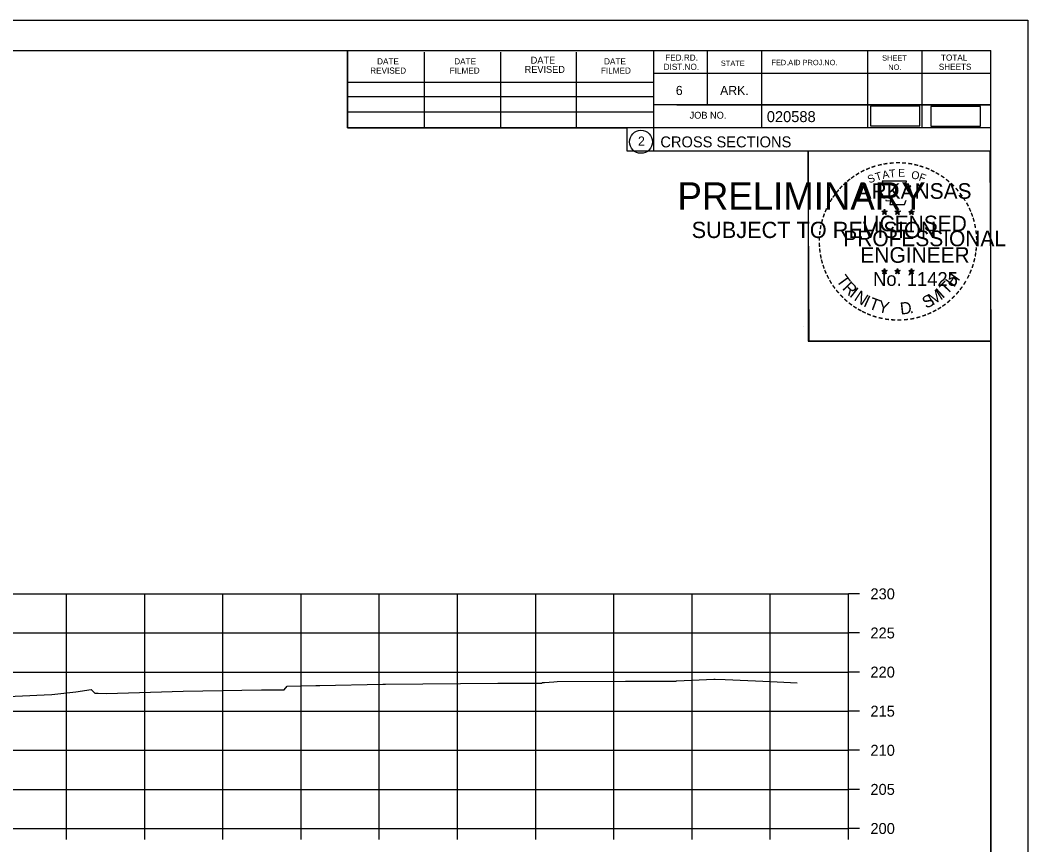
# Model space of a CAD drawing. Extents: x 1368968 to 1369915, y 377395 to 380381.
# Drawn here: x 1369785.9 to 1369914.7, y 378142.6 to 378248 of the extents above; entities that cross this region are included whole.
import ezdxf

# ---------------------------------------------------------------- set-up
doc = ezdxf.new("R2010")
doc.units = 0
for name, color, linetype in [('Default', 7, 'Continuous'), ('S_BREAKLINE_ANNOT', 7, 'Continuous'), ('S_BRIDGE', 7, 'Continuous'), ('S_BRIDGE_ANNOT', 7, 'Continuous'), ('S_BUILDING_ANNOT', 7, 'Continuous'), ('S_CAL_CORNER', 7, 'Continuous'), ('S_CTL_TABLE', 7, 'Continuous'), ('S_DITCHLINE_ANNOT', 7, 'Continuous'), ('S_DROP_INLET', 7, 'Continuous')]:
    doc.layers.add(name, color=color, linetype=linetype)

msp = doc.modelspace()

# ---------------------------------------------------------------- linework, layer by layer
at = {"layer": 'Default'}
for points in [[(1369894.57, 378234.53), (1369900.91, 378234.53), (1369900.91, 378237.05), (1369894.57, 378237.05)], [(1369902.31, 378234.48), (1369908.65, 378234.48), (1369908.65, 378237), (1369902.31, 378237)]]:
    msp.add_lwpolyline(points, close=True, dxfattribs=at)
at = {"layer": 'S_BREAKLINE_ANNOT'}
for p, q in [((1369891.78, 378144.69), (1369891.78, 378174.69)), ((1369893.18, 378174.69), (1369891.78, 378174.69)), ((1369893.18, 378169.69), (1369891.78, 378169.69)), ((1369893.18, 378164.69), (1369891.78, 378164.69)), ((1369893.18, 378159.69), (1369891.78, 378159.69)), ((1369893.18, 378154.69), (1369891.78, 378154.69)), ((1369893.18, 378149.69), (1369891.78, 378149.69)), ((1369611.78, 378144.69), (1369891.78, 378144.69)), ((1369791.78, 378143.29), (1369791.78, 378144.69)), ((1369801.78, 378143.29), (1369801.78, 378144.69)), ((1369811.78, 378143.29), (1369811.78, 378144.69)), ((1369821.78, 378143.29), (1369821.78, 378144.69)), ((1369831.78, 378143.29), (1369831.78, 378144.69)), ((1369841.78, 378143.29), (1369841.78, 378144.69)), ((1369851.78, 378143.29), (1369851.78, 378144.69)), ((1369861.78, 378143.29), (1369861.78, 378144.69)), ((1369871.78, 378143.29), (1369871.78, 378144.69)), ((1369881.78, 378143.29), (1369881.78, 378144.69)), ((1369891.78, 378143.29), (1369891.78, 378144.69)), ((1369893.18, 378144.69), (1369891.78, 378144.69))]:
    msp.add_line(p, q, dxfattribs=at)
at = {"layer": 'S_BRIDGE_ANNOT'}
for p, q in [((1369593.78, 378244.15), (1369909.96, 378244.15)), ((1369827.7, 378234.27), (1369827.7, 378244.15)), ((1369866.86, 378244.15), (1369866.86, 378231.35)), ((1369873.7, 378244.15), (1369873.7, 378237.21)), ((1369880.64, 378244.15), (1369880.64, 378234.27)), ((1369894.22, 378244.15), (1369894.22, 378234.27)), ((1369901.16, 378244.15), (1369901.16, 378234.27)), ((1369909.96, 378038.69), (1369909.96, 378244.15)), ((1369837.56, 378234.27), (1369837.56, 378243.95)), ((1369847.32, 378234.27), (1369847.32, 378243.95)), ((1369857, 378234.27), (1369857, 378243.95)), ((1369909.96, 378241.21), (1369866.86, 378241.21)), ((1369909.96, 378241.23), (1369909.96, 378241.23)), ((1369827.7, 378240.13), (1369866.86, 378240.13)), ((1369827.7, 378238.27), (1369866.86, 378238.27)), ((1369827.7, 378234.27), (1369827.7, 378236.33)), ((1369827.7, 378236.33), (1369866.86, 378236.33)), ((1369909.96, 378237.21), (1369866.86, 378237.21)), ((1369869.82, 378237.21), (1369909.96, 378237.21)), ((1369909.96, 378234.27), (1369827.7, 378234.27)), ((1369866.86, 378231.35), (1369909.96, 378231.35))]:
    msp.add_line(p, q, dxfattribs=at)
msp.add_circle((1369865.24, 378232.49), 1.47, dxfattribs=at)
at = {"layer": 'S_BUILDING_ANNOT'}
for p, q in [((1369896.04, 378223.61), (1369896.39, 378223.5)), ((1369896.04, 378223.61), (1369896.29, 378223.56)), ((1369896.04, 378223.61), (1369896.28, 378223.48)), ((1369896.17, 378223.2), (1369896.39, 378223.5)), ((1369896.17, 378223.2), (1369896.3, 378223.44)), ((1369896.39, 378223.86), (1369896.35, 378223.61)), ((1369896.39, 378223.5), (1369896.39, 378223.86)), ((1369896.39, 378223.86), (1369896.44, 378223.61)), ((1369896.74, 378223.61), (1369896.39, 378223.5)), ((1369896.6, 378223.2), (1369896.39, 378223.5)), ((1369896.74, 378223.61), (1369896.45, 378223.56)), ((1369896.6, 378223.2), (1369896.47, 378223.49)), ((1369896.74, 378223.61), (1369896.53, 378223.5)), ((1369897.71, 378223.61), (1369898.06, 378223.5)), ((1369897.71, 378223.61), (1369897.96, 378223.56)), ((1369897.71, 378223.61), (1369897.95, 378223.48)), ((1369897.84, 378223.2), (1369898.06, 378223.5)), ((1369897.84, 378223.2), (1369897.97, 378223.44)), ((1369898.06, 378223.86), (1369898.02, 378223.61)), ((1369898.06, 378223.5), (1369898.06, 378223.86)), ((1369898.06, 378223.86), (1369898.11, 378223.61)), ((1369898.41, 378223.61), (1369898.06, 378223.5)), ((1369898.27, 378223.2), (1369898.06, 378223.5)), ((1369898.41, 378223.61), (1369898.12, 378223.56)), ((1369898.27, 378223.2), (1369898.14, 378223.49)), ((1369898.41, 378223.61), (1369898.2, 378223.5)), ((1369899.48, 378223.59), (1369899.82, 378223.48)), ((1369899.48, 378223.59), (1369899.73, 378223.55)), ((1369899.48, 378223.59), (1369899.71, 378223.47)), ((1369899.61, 378223.19), (1369899.82, 378223.48)), ((1369899.61, 378223.19), (1369899.73, 378223.43)), ((1369899.82, 378223.85), (1369899.78, 378223.6)), ((1369899.82, 378223.48), (1369899.82, 378223.85)), ((1369899.82, 378223.85), (1369899.87, 378223.6)), ((1369900.17, 378223.59), (1369899.82, 378223.48)), ((1369900.04, 378223.19), (1369899.82, 378223.48)), ((1369900.17, 378223.59), (1369899.89, 378223.55)), ((1369900.04, 378223.19), (1369899.9, 378223.48)), ((1369900.17, 378223.59), (1369899.97, 378223.49)), ((1369896.17, 378223.2), (1369896.39, 378223.42)), ((1369896.6, 378223.2), (1369896.39, 378223.41)), ((1369897.84, 378223.2), (1369898.06, 378223.42)), ((1369898.27, 378223.2), (1369898.06, 378223.41)), ((1369899.61, 378223.19), (1369899.82, 378223.4)), ((1369900.04, 378223.19), (1369899.82, 378223.4)), ((1369896.04, 378216.03), (1369896.39, 378215.92)), ((1369896.04, 378216.03), (1369896.29, 378215.99)), ((1369896.04, 378216.03), (1369896.27, 378215.91)), ((1369896.17, 378215.63), (1369896.39, 378215.92)), ((1369896.17, 378215.63), (1369896.3, 378215.87)), ((1369896.17, 378215.63), (1369896.38, 378215.84)), ((1369896.39, 378216.29), (1369896.35, 378216.04)), ((1369896.6, 378215.63), (1369896.38, 378215.84)), ((1369896.39, 378215.92), (1369896.39, 378216.29)), ((1369896.39, 378216.29), (1369896.44, 378216.04)), ((1369896.73, 378216.03), (1369896.39, 378215.92)), ((1369896.6, 378215.63), (1369896.39, 378215.92)), ((1369896.73, 378216.03), (1369896.45, 378215.98)), ((1369896.6, 378215.63), (1369896.46, 378215.92)), ((1369896.73, 378216.03), (1369896.53, 378215.93)), ((1369897.71, 378216.03), (1369898.06, 378215.92)), ((1369897.71, 378216.03), (1369897.96, 378215.99)), ((1369897.71, 378216.03), (1369897.94, 378215.91)), ((1369897.84, 378215.63), (1369898.06, 378215.92)), ((1369897.84, 378215.63), (1369897.97, 378215.87)), ((1369897.84, 378215.63), (1369898.05, 378215.84)), ((1369898.06, 378216.29), (1369898.01, 378216.04)), ((1369898.27, 378215.63), (1369898.05, 378215.84)), ((1369898.06, 378215.92), (1369898.06, 378216.29)), ((1369898.06, 378216.29), (1369898.1, 378216.04)), ((1369898.4, 378216.03), (1369898.06, 378215.92)), ((1369898.27, 378215.63), (1369898.06, 378215.92)), ((1369898.4, 378216.03), (1369898.12, 378215.98)), ((1369898.27, 378215.63), (1369898.13, 378215.92)), ((1369898.4, 378216.03), (1369898.2, 378215.93)), ((1369899.47, 378216.02), (1369899.82, 378215.91)), ((1369899.47, 378216.02), (1369899.73, 378215.98)), ((1369899.47, 378216.02), (1369899.71, 378215.9)), ((1369899.61, 378215.62), (1369899.82, 378215.91)), ((1369899.61, 378215.62), (1369899.73, 378215.86)), ((1369899.61, 378215.62), (1369899.82, 378215.83)), ((1369899.82, 378216.28), (1369899.78, 378216.03)), ((1369899.82, 378215.91), (1369899.82, 378216.28)), ((1369899.82, 378216.28), (1369899.87, 378216.03)), ((1369900.17, 378216.02), (1369899.82, 378215.91)), ((1369900.04, 378215.62), (1369899.82, 378215.91)), ((1369900.04, 378215.62), (1369899.82, 378215.83)), ((1369900.17, 378216.02), (1369899.88, 378215.97)), ((1369900.04, 378215.62), (1369899.9, 378215.91)), ((1369900.17, 378216.02), (1369899.97, 378215.92))]:
    msp.add_line(p, q, dxfattribs=at)
for points in [[(1369896.08, 378227.48), (1369896.35, 378226.66)], [(1369899.59, 378226.56), (1369899.74, 378226.85), (1369899.05, 378226.82), (1369899.2, 378227.48), (1369896.08, 378227.48)], [(1369896.57, 378225.06), (1369896.57, 378224.97), (1369897.14, 378224.96), (1369897.08, 378224.48), (1369898.95, 378224.48), (1369899.15, 378225.02)], [(1369896.39, 378223.86), (1369896.6, 378223.2), (1369896.04, 378223.61), (1369896.74, 378223.61), (1369896.17, 378223.2), (1369896.39, 378223.86)], [(1369898.06, 378223.86), (1369898.27, 378223.2), (1369897.71, 378223.61), (1369898.41, 378223.61), (1369897.84, 378223.2), (1369898.06, 378223.86)], [(1369899.82, 378223.85), (1369900.04, 378223.19), (1369899.48, 378223.59), (1369900.17, 378223.59), (1369899.61, 378223.19), (1369899.82, 378223.85)], [(1369896.39, 378216.29), (1369896.6, 378215.63), (1369896.04, 378216.03), (1369896.73, 378216.03), (1369896.17, 378215.63), (1369896.39, 378216.29)], [(1369898.06, 378216.29), (1369898.27, 378215.63), (1369897.71, 378216.03), (1369898.4, 378216.03), (1369897.84, 378215.63), (1369898.06, 378216.29)], [(1369899.82, 378216.28), (1369900.04, 378215.62), (1369899.47, 378216.02), (1369900.17, 378216.02), (1369899.61, 378215.62), (1369899.82, 378216.28)]]:
    msp.add_lwpolyline(points, dxfattribs=at)
for centre, radius in [((1369896.39, 378223.49), 0.172), ((1369896.39, 378223.49), 0.145), ((1369896.39, 378223.49), 0.116), ((1369896.39, 378223.49), 0.0991), ((1369896.39, 378223.49), 0.0747), ((1369896.39, 378223.49), 0.0495), ((1369896.39, 378223.49), 0.0296), ((1369898.06, 378223.49), 0.172), ((1369898.06, 378223.49), 0.145), ((1369898.06, 378223.49), 0.116), ((1369898.06, 378223.49), 0.0991), ((1369898.06, 378223.49), 0.0747), ((1369898.06, 378223.49), 0.0495), ((1369898.06, 378223.49), 0.0296), ((1369899.82, 378223.48), 0.172), ((1369899.82, 378223.48), 0.145), ((1369899.82, 378223.48), 0.116), ((1369899.82, 378223.48), 0.0991), ((1369899.82, 378223.48), 0.0747), ((1369899.82, 378223.48), 0.0495), ((1369899.82, 378223.48), 0.0296), ((1369896.39, 378215.92), 0.172), ((1369896.39, 378215.92), 0.145), ((1369896.39, 378215.92), 0.116), ((1369896.39, 378215.92), 0.0991), ((1369896.39, 378215.92), 0.0747), ((1369896.39, 378215.92), 0.0495), ((1369896.39, 378215.92), 0.0296), ((1369898.05, 378215.92), 0.172), ((1369898.05, 378215.92), 0.145), ((1369898.05, 378215.92), 0.116), ((1369898.05, 378215.92), 0.0991), ((1369898.05, 378215.92), 0.0747), ((1369898.05, 378215.92), 0.0495), ((1369898.05, 378215.92), 0.0296), ((1369899.82, 378215.91), 0.172), ((1369899.82, 378215.91), 0.145), ((1369899.82, 378215.91), 0.116), ((1369899.82, 378215.91), 0.0991), ((1369899.82, 378215.91), 0.0747), ((1369899.82, 378215.91), 0.0495), ((1369899.82, 378215.91), 0.0296)]:
    msp.add_circle(centre, radius, dxfattribs=at)
at = {"layer": 'S_CTL_TABLE'}
msp.add_lwpolyline([(1369782.41, 378161.48), (1369788.93, 378161.8), (1369789.89, 378161.84), (1369792.99, 378162.18), (1369794.94, 378162.45), (1369795.3, 378162.12), (1369795.42, 378161.99), (1369795.84, 378161.99), (1369796.91, 378161.96), (1369802.52, 378162.13), (1369806.69, 378162.26), (1369816.72, 378162.41), (1369818, 378162.43), (1369819.41, 378162.4), (1369819.56, 378162.4), (1369819.6, 378162.44), (1369819.99, 378162.87), (1369823.66, 378162.98), (1369824.19, 378162.99), (1369832.25, 378163.13), (1369832.56, 378163.14), (1369846.92, 378163.28), (1369852.51, 378163.29), (1369852.63, 378163.36), (1369852.91, 378163.37), (1369854.09, 378163.46), (1369854.11, 378163.46), (1369854.51, 378163.47), (1369863.27, 378163.54), (1369869.69, 378163.51), (1369869.78, 378163.59), (1369869.78, 378163.59), (1369869.82, 378163.59), (1369874.54, 378163.8), (1369874.71, 378163.79), (1369876.02, 378163.73), (1369881.8, 378163.49), (1369885.21, 378163.3)], dxfattribs=at)
at = {"layer": 'S_DITCHLINE_ANNOT'}
for p, q in [((1369611.78, 378174.69), (1369891.78, 378174.69)), ((1369791.78, 378144.69), (1369791.78, 378174.69)), ((1369801.78, 378144.69), (1369801.78, 378174.69)), ((1369811.78, 378144.69), (1369811.78, 378174.69)), ((1369821.78, 378144.69), (1369821.78, 378174.69)), ((1369831.78, 378144.69), (1369831.78, 378174.69)), ((1369841.78, 378144.69), (1369841.78, 378174.69)), ((1369851.78, 378144.69), (1369851.78, 378174.69)), ((1369861.78, 378144.69), (1369861.78, 378174.69)), ((1369871.78, 378144.69), (1369871.78, 378174.69)), ((1369881.78, 378144.69), (1369881.78, 378174.69)), ((1369891.78, 378144.69), (1369891.78, 378174.69)), ((1369611.78, 378169.69), (1369891.78, 378169.69)), ((1369611.78, 378164.69), (1369891.78, 378164.69)), ((1369611.78, 378159.69), (1369891.78, 378159.69)), ((1369611.78, 378154.69), (1369891.78, 378154.69)), ((1369611.78, 378149.69), (1369891.78, 378149.69)), ((1369611.78, 378144.69), (1369891.78, 378144.69))]:
    msp.add_line(p, q, dxfattribs=at)
at = {"layer": 'S_DROP_INLET'}
for p, q in [((1369581.38, 378248.05), (1369914.71, 378248.05)), ((1369885.99, 378208.9), (1369885.99, 378208.9))]:
    msp.add_line(p, q, dxfattribs=at)
for points in [[(1369581.37, 378248.05), (1369914.71, 378248.05), (1369914.71, 378034.71), (1369581.37, 378034.71)], [(1369827.7, 378244.15), (1369827.7, 378234.27), (1369863.43, 378234.27), (1369863.43, 378231.35), (1369886.63, 378231.35), (1369886.63, 378207.02), (1369909.96, 378207.02), (1369909.96, 378038.69), (1369593.78, 378038.69), (1369593.78, 378244.15)], [(1369886.63, 378231.35), (1369909.84, 378231.35), (1369909.96, 378207.02), (1369886.75, 378207.02)]]:
    msp.add_lwpolyline(points, close=True, dxfattribs=at)

# ---------------------------------------------------------------- texts
at = {"layer": 'S_BRIDGE'}
for s, p in [('230', (1369894.58, 378173.99)), ('225', (1369894.58, 378168.99)), ('220', (1369894.58, 378163.99)), ('215', (1369894.58, 378158.99)), ('210', (1369894.58, 378153.99)), ('205', (1369894.58, 378148.99)), ('200', (1369894.58, 378143.99))]:
    msp.add_text(s, height=1.4, dxfattribs=at).set_placement(p)
at = {"layer": 'S_BRIDGE_ANNOT'}
for s, height, p in [('DATE', 0.782, (1369831.5, 378242.39)), ('DATE', 0.782, (1369841.36, 378242.39)), ('DATE', 0.879, (1369851.14, 378242.49)), ('DATE', 0.782, (1369860.52, 378242.39)), ('FED.RD.', 0.782, (1369868.34, 378242.87)), ('STATE', 0.684, (1369875.46, 378242.19)), ('FED.AID PROJ.NO.', 0.684, (1369881.92, 378242.29)), ('SHEET', 0.684, (1369896.08, 378242.87)), ('TOTAL', 0.782, (1369903.6, 378242.87)), ('REVISED', 0.782, (1369830.62, 378241.21)), ('FILMED', 0.782, (1369840.78, 378241.21)), ('REVISED', 0.879, (1369850.36, 378241.31)), ('FILMED', 0.782, (1369860.12, 378241.21)), ('DIST.NO.', 0.782, (1369868.14, 378241.69)), ('NO.', 0.684, (1369896.86, 378241.69)), ('SHEETS', 0.782, (1369903.32, 378241.69)), ('6', 1.17, (1369869.7, 378238.47)), ('ARK.', 1.172, (1369875.36, 378238.47)), ('JOB NO.', 0.879, (1369871.46, 378235.45)), ('020588', 1.4, (1369881.33, 378235.01)), ('2', 1.17, (1369864.86, 378232)), ('CROSS SECTIONS', 1.4, (1369867.72, 378231.78))]:
    msp.add_text(s, height=height, rotation=360, dxfattribs=at).set_placement(p)
at = {"layer": 'S_BUILDING_ANNOT'}
for s, height, rotation, p in [('-', 1.6, 5.8968, (1369896.99, 378229.12)), ('-', 1.6, 0.1862, (1369897.76, 378229.2)), ('-', 1.6, 357.743, (1369898.48, 378229.18)), ('-', 1.6, 34.0636, (1369892.97, 378227.66)), ('-', 1.6, 28.7918, (1369893.56, 378228.03)), ('-', 1.6, 24.3072, (1369894.2, 378228.34)), ('-', 1.6, 19.1761, (1369894.83, 378228.61)), ('T', 1, 16.4036, (1369895.35, 378227.49)), ('-', 1.6, 13.6301, (1369895.58, 378228.85)), ('A', 1, 11.2132, (1369896.18, 378227.74)), ('-', 1.6, 10.2193, (1369896.26, 378229.01)), ('T', 1, 6.0228, (1369897.03, 378227.91)), ('E', 1, 0.8323, (1369898.13, 378228.02)), ('-', 1.6, 352.1617, (1369899.23, 378229.13)), ('O', 1, 350.4515, (1369899.74, 378227.81)), ('-', 1.6, 347.2049, (1369899.95, 378229.01)), ('-', 1.6, 342.3362, (1369900.58, 378228.86)), ('-', 1.6, 337.8551, (1369901.32, 378228.64)), ('-', 1.6, 334.1211, (1369901.95, 378228.36)), ('-', 1.6, 329.6409, (1369902.53, 378228.08)), ('-', 1.6, 42.9622, (1369891.48, 378226.47)), ('-', 1.6, 38.9507, (1369891.91, 378226.88)), ('-', 1.6, 36.2317, (1369892.39, 378227.26)), ('S', 1, 21.594, (1369894.44, 378227.16)), ('F', 1, 340.0707, (1369900.69, 378227.58)), ('-', 1.6, 325.8627, (1369903.17, 378227.72)), ('-', 1.6, 320.5297, (1369903.78, 378227.29)), ('-', 1.6, 50.6142, (1369890.63, 378225.5)), ('-', 1.6, 48.423, (1369891.03, 378225.99)), ('ARKANSAS', 2, 360, (1369892.94, 378225.2)), ('-', 1.6, 315.5786, (1369904.38, 378226.81)), ('-', 1.6, 309.8797, (1369904.95, 378226.26)), ('-', 1.6, 58.0706, (1369889.89, 378224.41)), ('-', 1.6, 54.2325, (1369890.22, 378224.93)), ('-', 1.6, 306.6522, (1369905.47, 378225.65)), ('-', 1.4, 303.6753, (1369905.96, 378225.09)), ('-', 1.6, 299.6684, (1369906.28, 378224.48)), ('-', 1.6, 67.7743, (1369889.32, 378223.18)), ('-', 1.6, 62.8713, (1369889.58, 378223.79)), ('DWB', 0.01, 360, (1369896.38, 378223.49)), ('DWB', 0.01, 360, (1369898.05, 378223.49)), ('DWB', 0.01, 360, (1369899.81, 378223.48)), ('-', 1.6, 294.6628, (1369906.6, 378223.87)), ('-', 1.6, 290.5728, (1369906.86, 378223.29)), ('-', 1.6, 75.461, (1369888.9, 378221.84)), ('-', 1.6, 72.3945, (1369889.1, 378222.55)), ('LICENSED', 2, 360, (1369893.53, 378221.05)), ('-', 1.6, 285.1233, (1369907.09, 378222.71)), ('-', 1.6, 85.1863, (1369888.69, 378220.43)), ('-', 1.6, 81.2013, (1369888.77, 378221.13)), ('PROFESSIONAL', 2, 360, (1369891.11, 378219.14)), ('-', 1.6, 280.5493, (1369907.29, 378221.97)), ('-', 1.6, 276.5962, (1369907.45, 378221.2)), ('-', 1.6, 94.1959, (1369888.7, 378219.01)), ('-', 1.6, 89.0622, (1369888.67, 378219.73)), ('-', 1.6, 274.3301, (1369907.51, 378220.48)), ('-', 1.6, 269.9407, (1369907.55, 378219.85)), ('-', 1.6, 98.9479, (1369888.78, 378218.34)), ('ENGINEER', 2, 360, (1369893.3, 378217.02)), ('-', 1.6, 260.9953, (1369907.46, 378218.53)), ('-', 1.6, 263.5172, (1369907.53, 378219.18)), ('-', 1.6, 101.7149, (1369888.91, 378217.61)), ('-', 1.6, 105.4578, (1369889.07, 378217.01)), ('-', 1.6, 255.7626, (1369907.35, 378217.85)), ('-', 1.6, 109.0874, (1369889.29, 378216.38)), ('-', 1.6, 114.0643, (1369889.54, 378215.79)), ('No. 11425', 1.757, 360, (1369894.92, 378214.07)), ('DWB', 0.01, 360, (1369896.37, 378215.92)), ('DWB', 0.01, 360, (1369898.04, 378215.92)), ('DWB', 0.01, 360, (1369899.81, 378215.91)), ('H', 1.54, 54.6088, (1369905.27, 378213.8)), ('-', 1.6, 247.8887, (1369906.94, 378216.46)), ('-', 1.6, 252.8681, (1369907.17, 378217.13)), ('-', 1.6, 115.7289, (1369889.85, 378215.17)), ('-', 1.6, 120.4471, (1369890.2, 378214.58)), ('T', 1.54, 306.0406, (1369890.15, 378214.76)), ('R', 1.54, 314.005, (1369890.91, 378213.71)), ('T', 1.54, 46.6444, (1369904.38, 378212.85)), ('-', 1.6, 239.0712, (1369906.29, 378215.07)), ('-', 1.6, 244.6197, (1369906.68, 378215.83)), ('-', 1.6, 125.8934, (1369890.61, 378214.02)), ('-', 1.6, 130.7181, (1369891.07, 378213.47)), ('I', 1.54, 321.9694, (1369891.81, 378212.78)), ('N', 1.54, 326.5002, (1369892.38, 378212.31)), ('M', 1.54, 32.6563, (1369902.53, 378211.53)), ('I', 1.54, 42.1136, (1369903.81, 378212.37)), ('-', 1.6, 231.2538, (1369905.46, 378213.86)), ('-', 1.6, 233.8452, (1369905.89, 378214.42)), ('-', 1.6, 134.2238, (1369891.59, 378212.92)), ('-', 1.6, 138.9338, (1369892.11, 378212.46)), ('-', 1.6, 144.6463, (1369892.67, 378212.05)), ('I', 1.54, 335.3603, (1369893.58, 378211.52)), ('T', 1.54, 339.8912, (1369894.25, 378211.2)), ('Y', 1.54, 347.8556, (1369895.46, 378210.75)), ('D', 1.54, 6.3969, (1369898.45, 378210.39)), ('S', 1.54, 26.9312, (1369901.69, 378211.12)), ('-', 1.6, 221.0851, (1369904.45, 378212.78)), ('-', 1.6, 225.7653, (1369904.98, 378213.29)), ('-', 1.6, 148.0898, (1369893.23, 378211.68)), ('-', 1.6, 151.5704, (1369893.81, 378211.36)), ('-', 1.6, 154.6002, (1369894.33, 378211.11)), ('-', 1.6, 158.5612, (1369894.95, 378210.86)), ('.', 1.54, 13.7642, (1369899.64, 378210.52)), ('-', 1.6, 204.2516, (1369902.19, 378211.26)), ('-', 1.6, 207.3568, (1369902.81, 378211.58)), ('-', 1.6, 212.2491, (1369903.37, 378211.92)), ('-', 1.6, 215.7363, (1369903.91, 378212.31)), ('-', 1.6, 162.7983, (1369895.64, 378210.64)), ('-', 1.6, 167.5555, (1369896.36, 378210.48)), ('-', 1.6, 173.1155, (1369897.13, 378210.37)), ('-', 1.6, 176.5183, (1369897.88, 378210.32)), ('-', 1.6, 181.5918, (1369898.62, 378210.34)), ('-', 1.6, 185.8167, (1369899.43, 378210.41)), ('-', 1.6, 191.2858, (1369900.16, 378210.54)), ('-', 1.6, 195.4743, (1369900.89, 378210.74)), ('-', 1.6, 200.7184, (1369901.57, 378210.99))]:
    msp.add_text(s, height=height, rotation=rotation, dxfattribs=at).set_placement(p)
at = {"layer": 'S_CAL_CORNER'}
for s, height, p in [('PRELIMINARY', 3.5, (1369869.91, 378223.81)), ('DWB', 0.01, (1369870.65, 378225.66)), ('SUBJECT TO REVISION', 2.0751, (1369871.72, 378220.19))]:
    msp.add_text(s, height=height, rotation=360, dxfattribs=at).set_placement(p)

doc.saveas('drawing.dxf')
